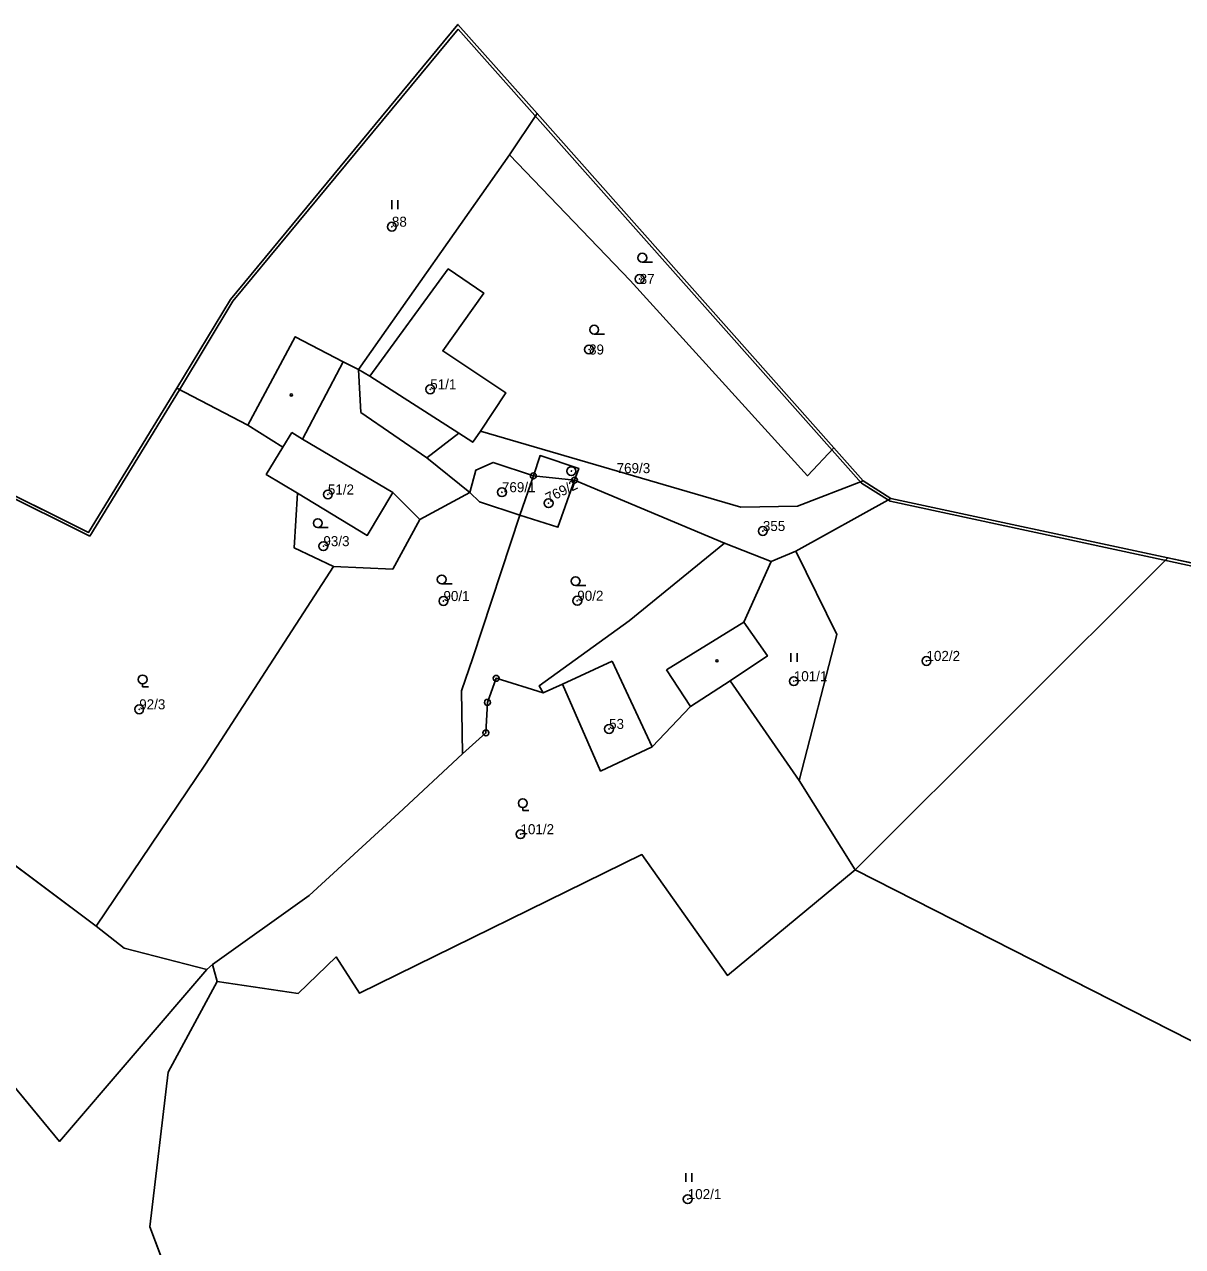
# Model space of a CAD drawing. Extents: x -652854 to -650068, y -1097661 to -1095417.
# Drawn here: x -650437 to -650241, y -1095838.2 to -1095631.3 of the extents above; entities that cross this region are included whole.
import ezdxf

# ---------------------------------------------------------------- set-up
doc = ezdxf.new("R2010")
doc.units = 0
for name, color, linetype in [('Definiční body parcel', 7, 'Continuous'), ('Geodetické body', 7, 'Continuous'), ('Hranice - vnitř_ kresba', 7, 'Continuous'), ('Hranice obcí', 7, 'Continuous'), ('Hranice parcel', 7, 'Continuous'), ('Obvody jako plochy', 7, 'Continuous'), ('Ostatní hranice', 7, 'Continuous'), ('Parcelní čísla', 7, 'Continuous'), ('Prvky pro prodl_ par_ č_', 7, 'Continuous'), ('Značky kultur', 7, 'Continuous'), ('Značky na budově ne v SPI', 7, 'Continuous')]:
    doc.layers.add(name, color=color, linetype=linetype)

msp = doc.modelspace()

# ---------------------------------------------------------------- linework, layer by layer
at = {"layer": 'Definiční body parcel'}
for centre, radius in [((-650374.83, -1095665.58), 0.75), ((-650374.83, -1095665.58), 0.0327), ((-650332.88, -1095674.42), 0.75), ((-650332.88, -1095674.42), 0.0327), ((-650341.45, -1095686.36), 0.75), ((-650341.45, -1095686.36), 0.0327), ((-650368.34, -1095693.1), 0.75), ((-650368.34, -1095693.1), 0.0327), ((-650344.44, -1095706.95), 0.75), ((-650344.44, -1095706.95), 0.0327), ((-650356.2, -1095710.52), 0.75), ((-650385.67, -1095710.91), 0.75), ((-650385.67, -1095710.91), 0.0327), ((-650356.2, -1095710.52), 0.0327), ((-650348.3, -1095712.37), 0.75), ((-650348.3, -1095712.37), 0.0327), ((-650312.02, -1095717.09), 0.75), ((-650312.02, -1095717.09), 0.0327), ((-650386.43, -1095719.65), 0.75), ((-650386.43, -1095719.65), 0.0327), ((-650366.1, -1095728.94), 0.75), ((-650343.44, -1095728.89), 0.75), ((-650366.1, -1095728.94), 0.0327), ((-650343.44, -1095728.89), 0.0327), ((-650284.32, -1095739.08), 0.75), ((-650284.32, -1095739.08), 0.0327), ((-650306.78, -1095742.51), 0.75), ((-650306.78, -1095742.51), 0.0327), ((-650417.61, -1095747.27), 0.75), ((-650417.61, -1095747.27), 0.0327), ((-650338.06, -1095750.59), 0.75), ((-650338.06, -1095750.59), 0.0327), ((-650353.06, -1095768.41), 0.75), ((-650353.06, -1095768.41), 0.0327), ((-650324.74, -1095830.18), 0.75), ((-650324.74, -1095830.18), 0.0327)]:
    msp.add_circle(centre, radius, dxfattribs=at)
at = {"layer": 'Geodetické body'}
for centre, radius in [((-650350.88, -1095707.74), 0.5), ((-650350.88, -1095707.74), 0.001), ((-650343.91, -1095708.48), 0.5), ((-650343.91, -1095708.48), 0.001), ((-650357.18, -1095742.02), 0.5), ((-650357.18, -1095742.02), 0.001), ((-650358.66, -1095746.09), 0.5), ((-650358.66, -1095746.09), 0.001), ((-650358.91, -1095751.26), 0.5), ((-650358.91, -1095751.26), 0.001)]:
    msp.add_circle(centre, radius, dxfattribs=at)
at = {"layer": 'Hranice - vnitř_ kresba'}
for p, q in [((-650389.96, -1095701.52), (-650383.06, -1095688.43)), ((-650378.55, -1095690.89), (-650363.49, -1095700.5)), ((-650393.28, -1095702.87), (-650391.76, -1095700.43)), ((-650391.76, -1095700.43), (-650389.96, -1095701.52)), ((-650389.96, -1095701.52), (-650374.66, -1095710.58)), ((-650328.36, -1095740.6), (-650315.23, -1095732.51)), ((-650345.97, -1095743.02), (-650337.54, -1095739.14)), ((-650337.54, -1095739.14), (-650330.74, -1095753.64)), ((-650324.27, -1095746.78), (-650328.36, -1095740.6))]:
    msp.add_line(p, q, dxfattribs=at)
at = {"layer": 'Hranice obcí'}
for p, q in [((-650402.17, -1095677.9), (-650363.64, -1095631.34)), ((-650363.64, -1095631.34), (-650350.22, -1095646.4)), ((-650350.22, -1095646.4), (-650299.98, -1095703.02)), ((-650411.23, -1095692.93), (-650402.17, -1095677.9)), ((-650426.17, -1095717.32), (-650411.23, -1095692.93)), ((-650463.84, -1095698.61), (-650426.17, -1095717.32)), ((-650299.98, -1095703.02), (-650295.06, -1095708.57)), ((-650295.06, -1095708.57), (-650290.35, -1095711.56)), ((-650243.45, -1095721.6), (-650290.35, -1095711.56)), ((-650243.45, -1095721.6), (-650216.76, -1095727.42))]:
    msp.add_line(p, q, dxfattribs=at)
at = {"layer": 'Hranice parcel'}
for p, q in [((-650350.22, -1095646.4), (-650354.9, -1095653.43)), ((-650354.9, -1095653.43), (-650380.5, -1095689.77)), ((-650354.9, -1095653.43), (-650334.48, -1095674.68)), ((-650365.3, -1095672.72), (-650378.55, -1095690.89)), ((-650359.28, -1095676.82), (-650365.3, -1095672.72)), ((-650334.48, -1095674.68), (-650304.49, -1095707.74)), ((-650366.22, -1095686.59), (-650359.28, -1095676.82)), ((-650391.2, -1095684.19), (-650399.21, -1095699.18)), ((-650383.06, -1095688.43), (-650391.2, -1095684.19)), ((-650355.56, -1095693.68), (-650366.22, -1095686.59)), ((-650380.5, -1095689.77), (-650383.06, -1095688.43)), ((-650380.5, -1095689.77), (-650380.11, -1095697)), ((-650380.5, -1095689.77), (-650378.55, -1095690.89)), ((-650411.23, -1095692.93), (-650399.21, -1095699.18)), ((-650359.82, -1095700.21), (-650355.56, -1095693.68)), ((-650380.11, -1095697), (-650368.89, -1095704.71)), ((-650399.21, -1095699.18), (-650393.28, -1095702.87)), ((-650368.89, -1095704.71), (-650363.49, -1095700.5)), ((-650363.49, -1095700.5), (-650361.13, -1095702.06)), ((-650359.82, -1095700.21), (-650361.13, -1095702.06)), ((-650315.77, -1095713.07), (-650359.82, -1095700.21)), ((-650393.28, -1095702.87), (-650396.11, -1095707.5)), ((-650304.49, -1095707.74), (-650299.98, -1095703.02)), ((-650361.65, -1095710.58), (-650368.89, -1095704.71)), ((-650357.66, -1095705.48), (-650360.61, -1095706.77)), ((-650350.88, -1095707.74), (-650357.66, -1095705.48)), ((-650349.74, -1095704.32), (-650350.88, -1095707.74)), ((-650343.2, -1095706.49), (-650349.74, -1095704.32)), ((-650390.82, -1095710.69), (-650396.11, -1095707.5)), ((-650360.61, -1095706.77), (-650361.65, -1095710.58)), ((-650350.88, -1095707.74), (-650353.18, -1095714.39)), ((-650343.91, -1095708.48), (-650350.88, -1095707.74)), ((-650343.91, -1095708.48), (-650343.2, -1095706.49)), ((-650343.91, -1095708.48), (-650346.73, -1095716.45)), ((-650318.52, -1095719.14), (-650343.91, -1095708.48)), ((-650295.06, -1095708.57), (-650306.16, -1095712.88)), ((-650391.37, -1095719.95), (-650390.82, -1095710.69)), ((-650378.99, -1095717.83), (-650390.82, -1095710.69)), ((-650374.66, -1095710.58), (-650378.99, -1095717.83)), ((-650370.12, -1095715.15), (-650374.66, -1095710.58)), ((-650370.12, -1095715.15), (-650361.65, -1095710.58)), ((-650361.65, -1095710.58), (-650359.97, -1095712.14)), ((-650359.97, -1095712.14), (-650353.18, -1095714.39)), ((-650306.46, -1095720.48), (-650290.35, -1095711.56)), ((-650306.16, -1095712.88), (-650315.77, -1095713.07)), ((-650374.69, -1095723.53), (-650370.12, -1095715.15)), ((-650353.18, -1095714.39), (-650361.14, -1095738.55)), ((-650346.73, -1095716.45), (-650353.18, -1095714.39)), ((-650384.69, -1095723.07), (-650391.37, -1095719.95)), ((-650318.52, -1095719.14), (-650334.65, -1095732.29)), ((-650310.62, -1095722.27), (-650318.52, -1095719.14)), ((-650315.23, -1095732.51), (-650310.62, -1095722.27)), ((-650310.62, -1095722.27), (-650306.46, -1095720.48)), ((-650306.46, -1095720.48), (-650299.49, -1095734.63)), ((-650296.41, -1095774.45), (-650243.45, -1095721.6)), ((-650406.4, -1095756.55), (-650384.69, -1095723.07)), ((-650384.69, -1095723.07), (-650374.69, -1095723.53)), ((-650334.65, -1095732.29), (-650349.89, -1095743.29)), ((-650315.23, -1095732.51), (-650311.24, -1095738.22)), ((-650299.49, -1095734.63), (-650305.86, -1095759.34)), ((-650361.14, -1095738.55), (-650363.05, -1095744.15)), ((-650311.24, -1095738.22), (-650317.53, -1095742.45)), ((-650358.66, -1095746.09), (-650357.18, -1095742.02)), ((-650357.18, -1095742.02), (-650349.23, -1095744.5)), ((-650349.23, -1095744.5), (-650345.97, -1095743.02)), ((-650339.5, -1095757.71), (-650345.97, -1095743.02)), ((-650317.53, -1095742.45), (-650324.27, -1095746.78)), ((-650305.86, -1095759.34), (-650317.53, -1095742.45)), ((-650363.05, -1095744.15), (-650362.9, -1095754.83)), ((-650349.89, -1095743.29), (-650349.23, -1095744.5)), ((-650358.91, -1095751.26), (-650358.66, -1095746.09)), ((-650330.74, -1095753.64), (-650324.27, -1095746.78)), ((-650362.9, -1095754.83), (-650358.91, -1095751.26)), ((-650373.63, -1095764.84), (-650362.9, -1095754.83)), ((-650330.74, -1095753.64), (-650339.5, -1095757.71)), ((-650424.91, -1095783.97), (-650406.4, -1095756.55)), ((-650305.86, -1095759.34), (-650296.41, -1095774.45)), ((-650388.84, -1095778.76), (-650373.63, -1095764.84)), ((-650446.64, -1095767.71), (-650424.91, -1095783.97)), ((-650332.5, -1095771.86), (-650380.34, -1095795.33)), ((-650318.03, -1095792.3), (-650332.5, -1095771.86)), ((-650296.41, -1095774.45), (-650318.03, -1095792.3)), ((-650189.59, -1095828.72), (-650296.41, -1095774.45)), ((-650464.66, -1095779.87), (-650431.1, -1095820.4)), ((-650405.21, -1095790.46), (-650388.84, -1095778.76)), ((-650424.91, -1095783.97), (-650420.14, -1095787.7)), ((-650420.14, -1095787.7), (-650406.15, -1095791.32)), ((-650406.15, -1095791.32), (-650405.21, -1095790.46)), ((-650404.41, -1095793.36), (-650405.21, -1095790.46)), ((-650384.29, -1095789.19), (-650390.71, -1095795.38)), ((-650380.34, -1095795.33), (-650384.29, -1095789.19)), ((-650431.1, -1095820.4), (-650406.15, -1095791.32)), ((-650404.41, -1095793.36), (-650412.7, -1095808.67)), ((-650390.71, -1095795.38), (-650404.41, -1095793.36)), ((-650412.7, -1095808.67), (-650415.8, -1095834.87)), ((-650415.8, -1095834.87), (-650409.55, -1095851.54))]:
    msp.add_line(p, q, dxfattribs=at)
at = {"layer": 'Obvody jako plochy'}
for points in [[(-650354.9, -1095653.43), (-650350.22, -1095646.4), (-650363.64, -1095631.34), (-650402.17, -1095677.9), (-650411.23, -1095692.93), (-650399.21, -1095699.18), (-650391.2, -1095684.19), (-650383.06, -1095688.43), (-650380.5, -1095689.77)], [(-650350.22, -1095646.4), (-650354.9, -1095653.43), (-650334.48, -1095674.68), (-650304.49, -1095707.74), (-650299.98, -1095703.02)], [(-650306.16, -1095712.88), (-650295.06, -1095708.57), (-650299.98, -1095703.02), (-650304.49, -1095707.74), (-650334.48, -1095674.68), (-650354.9, -1095653.43), (-650380.5, -1095689.77), (-650378.55, -1095690.89), (-650365.3, -1095672.72), (-650359.28, -1095676.82), (-650366.22, -1095686.59), (-650355.56, -1095693.68), (-650359.82, -1095700.21), (-650315.77, -1095713.07)], [(-650359.82, -1095700.21), (-650355.56, -1095693.68), (-650366.22, -1095686.59), (-650359.28, -1095676.82), (-650365.3, -1095672.72), (-650378.55, -1095690.89), (-650380.5, -1095689.77), (-650380.11, -1095697), (-650368.89, -1095704.71), (-650363.49, -1095700.5), (-650361.13, -1095702.06)], [(-650370.12, -1095715.15), (-650361.65, -1095710.58), (-650368.89, -1095704.71), (-650380.11, -1095697), (-650380.5, -1095689.77), (-650383.06, -1095688.43), (-650391.2, -1095684.19), (-650399.21, -1095699.18), (-650393.28, -1095702.87), (-650396.11, -1095707.5), (-650390.82, -1095710.69), (-650378.99, -1095717.83), (-650374.66, -1095710.58)], [(-650411.23, -1095692.93), (-650426.17, -1095717.32), (-650463.84, -1095698.61), (-650468.3, -1095741.3), (-650446.64, -1095767.71), (-650424.91, -1095783.97), (-650406.4, -1095756.55), (-650384.69, -1095723.07), (-650391.37, -1095719.95), (-650390.82, -1095710.69), (-650396.11, -1095707.5), (-650393.28, -1095702.87), (-650399.21, -1095699.18)], [(-650310.62, -1095722.27), (-650306.46, -1095720.48), (-650290.35, -1095711.56), (-650295.06, -1095708.57), (-650306.16, -1095712.88), (-650315.77, -1095713.07), (-650359.82, -1095700.21), (-650361.13, -1095702.06), (-650363.49, -1095700.5), (-650368.89, -1095704.71), (-650361.65, -1095710.58), (-650360.61, -1095706.77), (-650357.66, -1095705.48), (-650350.88, -1095707.74), (-650349.74, -1095704.32), (-650343.2, -1095706.49), (-650343.91, -1095708.48), (-650318.52, -1095719.14)], [(-650350.88, -1095707.74), (-650357.66, -1095705.48), (-650360.61, -1095706.77), (-650361.65, -1095710.58), (-650359.97, -1095712.14), (-650353.18, -1095714.39)], [(-650343.91, -1095708.48), (-650343.2, -1095706.49), (-650349.74, -1095704.32), (-650350.88, -1095707.74)], [(-650343.91, -1095708.48), (-650350.88, -1095707.74), (-650353.18, -1095714.39), (-650346.73, -1095716.45)], [(-650353.18, -1095714.39), (-650361.14, -1095738.55), (-650363.05, -1095744.15), (-650362.9, -1095754.83), (-650358.91, -1095751.26), (-650358.66, -1095746.09), (-650357.18, -1095742.02), (-650349.23, -1095744.5), (-650349.89, -1095743.29), (-650334.65, -1095732.29), (-650318.52, -1095719.14), (-650343.91, -1095708.48), (-650346.73, -1095716.45)], [(-650353.18, -1095714.39), (-650359.97, -1095712.14), (-650361.65, -1095710.58), (-650370.12, -1095715.15), (-650374.69, -1095723.53), (-650384.69, -1095723.07), (-650406.4, -1095756.55), (-650424.91, -1095783.97), (-650420.14, -1095787.7), (-650406.15, -1095791.32), (-650405.21, -1095790.46), (-650388.84, -1095778.76), (-650373.63, -1095764.84), (-650362.9, -1095754.83), (-650363.05, -1095744.15), (-650361.14, -1095738.55)], [(-650384.69, -1095723.07), (-650374.69, -1095723.53), (-650370.12, -1095715.15), (-650374.66, -1095710.58), (-650378.99, -1095717.83), (-650390.82, -1095710.69), (-650391.37, -1095719.95)], [(-650305.86, -1095759.34), (-650296.41, -1095774.45), (-650243.45, -1095721.6), (-650290.35, -1095711.56), (-650306.46, -1095720.48), (-650299.49, -1095734.63)], [(-650349.23, -1095744.5), (-650345.97, -1095743.02), (-650339.5, -1095757.71), (-650330.74, -1095753.64), (-650324.27, -1095746.78), (-650317.53, -1095742.45), (-650311.24, -1095738.22), (-650315.23, -1095732.51), (-650310.62, -1095722.27), (-650318.52, -1095719.14), (-650334.65, -1095732.29), (-650349.89, -1095743.29)], [(-650315.23, -1095732.51), (-650311.24, -1095738.22), (-650317.53, -1095742.45), (-650305.86, -1095759.34), (-650299.49, -1095734.63), (-650306.46, -1095720.48), (-650310.62, -1095722.27)], [(-650216.76, -1095727.42), (-650243.45, -1095721.6), (-650296.41, -1095774.45), (-650189.59, -1095828.72), (-650169.66, -1095786.41), (-650164.66, -1095765.89), (-650158.87, -1095749.95), (-650160.2, -1095747.49), (-650172.22, -1095739.93), (-650190.73, -1095734.05)], [(-650420.14, -1095787.7), (-650424.91, -1095783.97), (-650446.64, -1095767.71), (-650468.3, -1095741.3), (-650480.27, -1095760.26), (-650464.66, -1095779.87), (-650431.1, -1095820.4), (-650406.15, -1095791.32)], [(-650405.21, -1095790.46), (-650404.41, -1095793.36), (-650390.71, -1095795.38), (-650384.29, -1095789.19), (-650380.34, -1095795.33), (-650332.5, -1095771.86), (-650318.03, -1095792.3), (-650296.41, -1095774.45), (-650305.86, -1095759.34), (-650317.53, -1095742.45), (-650324.27, -1095746.78), (-650330.74, -1095753.64), (-650339.5, -1095757.71), (-650345.97, -1095743.02), (-650349.23, -1095744.5), (-650357.18, -1095742.02), (-650358.66, -1095746.09), (-650358.91, -1095751.26), (-650362.9, -1095754.83), (-650373.63, -1095764.84), (-650388.84, -1095778.76)], [(-650318.03, -1095792.3), (-650332.5, -1095771.86), (-650380.34, -1095795.33), (-650384.29, -1095789.19), (-650390.71, -1095795.38), (-650404.41, -1095793.36), (-650412.7, -1095808.67), (-650415.8, -1095834.87), (-650409.55, -1095851.54), (-650399.87, -1095862.15), (-650389.75, -1095872.8), (-650374.95, -1095883.69), (-650363.46, -1095882.3), (-650295.45, -1095857.4), (-650246.6, -1095852.26), (-650228.23, -1095846.5), (-650207.69, -1095837.1), (-650190.42, -1095830.87), (-650189.59, -1095828.72), (-650296.41, -1095774.45)], [(-650406.15, -1095791.32), (-650431.1, -1095820.4), (-650464.66, -1095779.87), (-650467.96, -1095793.34), (-650471.89, -1095808.33), (-650476.53, -1095813.53), (-650494.84, -1095839.58), (-650499.26, -1095849.08), (-650487.46, -1095903.53), (-650470.26, -1095905.62), (-650456.75, -1095891.76), (-650441.52, -1095882.55), (-650432.6, -1095881.88), (-650408.98, -1095891.11), (-650398.66, -1095892.26), (-650382.62, -1095893.79), (-650374.95, -1095883.69), (-650389.75, -1095872.8), (-650399.87, -1095862.15), (-650409.55, -1095851.54), (-650415.8, -1095834.87), (-650412.7, -1095808.67), (-650404.41, -1095793.36), (-650405.21, -1095790.46)]]:
    msp.add_lwpolyline(points, close=True, dxfattribs=at)
at = {"layer": 'Ostatní hranice'}
for p, q in [((-650401.74, -1095678.17), (-650363.63, -1095632.12)), ((-650363.63, -1095632.12), (-650350.61, -1095646.73)), ((-650350.61, -1095646.73), (-650295.33, -1095709)), ((-650410.8, -1095693.21), (-650401.74, -1095678.18)), ((-650425.98, -1095717.98), (-650410.8, -1095693.21)), ((-650463.94, -1095699.11), (-650425.98, -1095717.98)), ((-650295.33, -1095709), (-650290.49, -1095712.05)), ((-650290.49, -1095712.05), (-650243.52, -1095722.11)), ((-650243.52, -1095722.11), (-650216.87, -1095727.92))]:
    msp.add_line(p, q, dxfattribs=at)
at = {"layer": 'Značky kultur'}
for p, q in [((-650374.867, -1095661.085), (-650374.867, -1095662.585)), ((-650373.845, -1095662.585), (-650373.845, -1095661.085)), ((-650330.69, -1095671.58), (-650332.44, -1095671.58)), ((-650338.83, -1095683.76), (-650340.58, -1095683.76)), ((-650385.63, -1095716.51), (-650387.38, -1095716.51)), ((-650364.64, -1095726.04), (-650366.39, -1095726.04)), ((-650341.98, -1095726.32), (-650343.73, -1095726.32)), ((-650307.257, -1095737.735), (-650307.257, -1095739.235)), ((-650306.235, -1095739.235), (-650306.235, -1095737.735)), ((-650417.04, -1095742.96), (-650417.04, -1095743.46)), ((-650417.04, -1095743.46), (-650416.017, -1095743.46)), ((-650352.67, -1095763.91), (-650352.67, -1095764.41)), ((-650352.67, -1095764.41), (-650351.647, -1095764.41)), ((-650325.067, -1095825.775), (-650325.067, -1095827.275)), ((-650324.045, -1095827.275), (-650324.045, -1095825.775))]:
    msp.add_line(p, q, dxfattribs=at)
for centre in [(-650332.44, -1095670.83), (-650340.58, -1095683.01), (-650387.38, -1095715.76), (-650366.39, -1095725.29), (-650343.73, -1095725.57), (-650417.04, -1095742.21), (-650352.67, -1095763.16)]:
    msp.add_circle(centre, 0.75, dxfattribs=at)
at = {"layer": 'Značky na budově ne v SPI'}
for centre in [(-650391.86, -1095694.06), (-650319.78, -1095739.07)]:
    msp.add_circle(centre, 0.175, dxfattribs=at)

# ---------------------------------------------------------------- texts
at = {"layer": 'Parcelní čísla'}
for s, height, p in [('88', 1.7, (-650374.83, -1095665.58)), ('87', 1.7, (-650332.88, -1095675.27)), ('89', 1.7, (-650341.45, -1095687.21)), ('51/1', 1.7, (-650368.34, -1095693.1)), ('769/3', 0.1, (-650344.44, -1095706.95)), ('51/2', 1.7, (-650385.67, -1095710.91)), ('769/1', 1.7, (-650356.2, -1095710.52)), ('355', 1.7, (-650312.02, -1095717.09)), ('93/3', 1.7, (-650386.43, -1095719.65)), ('90/1', 1.7, (-650366.1, -1095728.94)), ('90/2', 1.7, (-650343.44, -1095728.89)), ('102/2', 1.7, (-650284.32, -1095739.08)), ('101/1', 1.7, (-650306.78, -1095742.51)), ('92/3', 1.7, (-650417.61, -1095747.27)), ('53', 1.7, (-650338.06, -1095750.59)), ('101/2', 1.7, (-650353.06, -1095768.41)), ('102/1', 1.7, (-650324.74, -1095830.18))]:
    msp.add_text(s, height=height, dxfattribs=at).set_placement(p)
msp.add_text('769/2', height=1.7, rotation=26.568, dxfattribs=at).set_placement((-650348.3, -1095712.37))
at = {"layer": 'Prvky pro prodl_ par_ č_'}
msp.add_text('769/3', height=1.7, dxfattribs=at).set_placement((-650336.78, -1095707.29))

doc.saveas('drawing.dxf')
